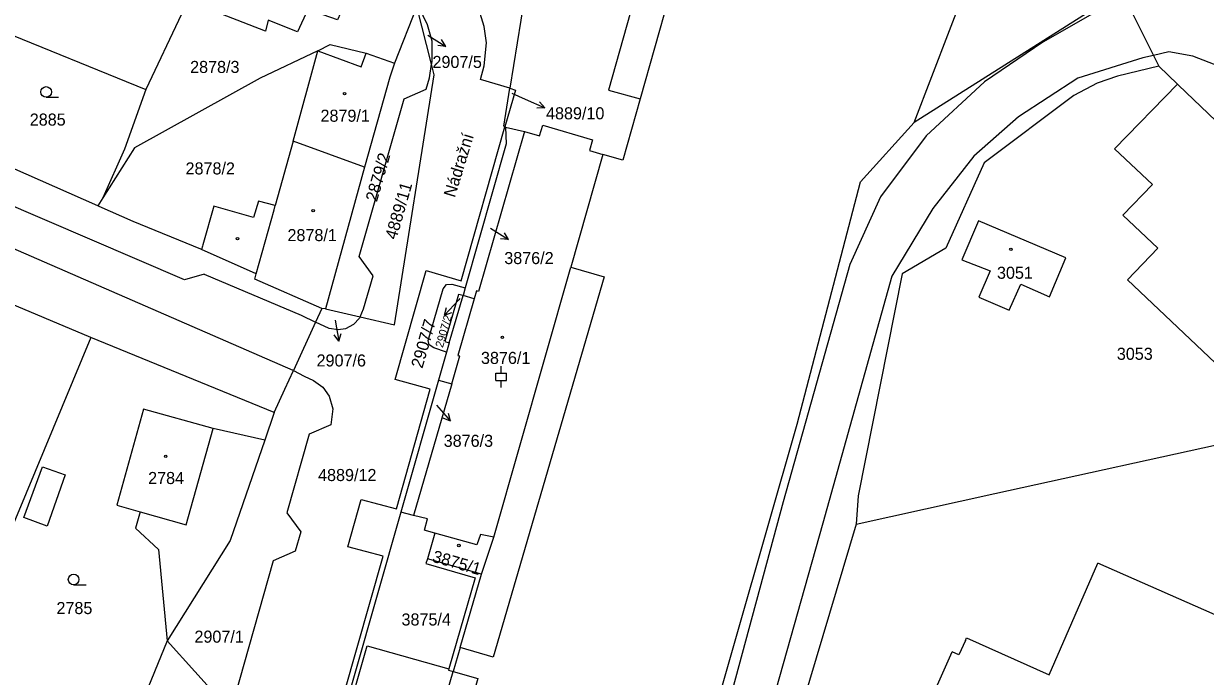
# Model space of a CAD drawing. Extents: x -527335 to -526256, y -1079142 to -1077809.
# Drawn here: x -526891.4 to -526725, y -1078806.1 to -1078714.2 of the extents above; entities that cross this region are included whole.
import ezdxf

# ---------------------------------------------------------------- set-up
doc = ezdxf.new("R2010")
doc.units = 0
for name, color, linetype in [('Vrstva 1', 7, 'Continuous'), ('Vrstva 2', 7, 'Continuous'), ('Vrstva 3', 7, 'Continuous'), ('Vrstva 4', 7, 'Continuous'), ('Vrstva 5', 7, 'Continuous'), ('Vrstva 7', 7, 'Continuous')]:
    doc.layers.add(name, color=color, linetype=linetype)

msp = doc.modelspace()

# ---------------------------------------------------------------- linework, layer by layer
at = {"layer": 'Vrstva 1'}
for p, q in [((-526796.21, -1078695.13), (-526804.6, -1078724.76)), ((-526819.43, -1078701.36), (-526822.95, -1078723.3)), ((-526736.78, -1078709.62), (-526766.02, -1078728.13)), ((-526836.05, -1078711.79), (-526839.19, -1078719.76)), ((-526833.99, -1078719.88), (-526836.05, -1078711.79)), ((-526853.47, -1078730.76), (-526850, -1078718.03)), ((-526833.92, -1078719.44), (-526833.99, -1078719.88)), ((-526834.28, -1078721.82), (-526833.99, -1078719.88)), ((-526833.6, -1078721.4), (-526833.99, -1078719.88)), ((-526728.91, -1078722.73), (-526731.58, -1078720.17)), ((-526839.2, -1078756.6), (-526833.6, -1078721.4)), ((-526823.64, -1078728.74), (-526823.55, -1078728.79)), ((-526823.55, -1078728.79), (-526820.87, -1078729.39)), ((-526880.94, -1078739.86), (-526903.84, -1078729.73)), ((-526843.4, -1078734.39), (-526853.47, -1078730.76)), ((-526843.4, -1078734.39), (-526848.91, -1078754.35)), ((-526880.24, -1078738.74), (-526880.94, -1078739.86)), ((-526881.96, -1078758.41), (-526909.05, -1078746.98)), ((-526831.48, -1078759.12), (-526829.54, -1078752.49)), ((-526849.41, -1078754.29), (-526850.31, -1078756.25)), ((-526848.91, -1078754.35), (-526849.41, -1078754.29)), ((-526848.91, -1078754.35), (-526844.03, -1078755.48)), ((-526844.03, -1078755.48), (-526843.54, -1078754.36)), ((-526850.31, -1078756.25), (-526853.42, -1078763.04)), ((-526844.03, -1078755.48), (-526844.11, -1078755.67)), ((-526844.03, -1078755.48), (-526839.2, -1078756.6)), ((-526881.96, -1078758.41), (-526900.23, -1078802.31)), ((-526856.12, -1078768.95), (-526881.96, -1078758.41)), ((-526832.99, -1078764.38), (-526838.29, -1078782.98)), ((-526856.12, -1078768.95), (-526857.46, -1078772.84)), ((-526836.49, -1078783.47), (-526838.29, -1078782.98)), ((-526774.18, -1078784.68), (-526790.21, -1078838.32)), ((-526871.22, -1078801.11), (-526877.03, -1078815.27)), ((-526863.41, -1078809.75), (-526871.22, -1078801.11)), ((-526829.95, -1078802.05), (-526830.92, -1078805.41))]:
    msp.add_line(p, q, dxfattribs=at)
for points in [[(-526766.02, -1078728.13), (-526758.54, -1078708.63), (-526747.6, -1078675.03)], [(-526796.21, -1078695.13), (-526797.53, -1078694.71), (-526797.63, -1078695.06), (-526800.78, -1078694.21), (-526809.06, -1078723.54), (-526804.6, -1078724.76)], [(-526822.95, -1078723.3), (-526827.09, -1078722.05), (-526826.54, -1078720.12), (-526826.24, -1078716.92), (-526826.57, -1078714.61), (-526827.31, -1078712.18), (-526828.95, -1078709.32), (-526834.61, -1078701.38)], [(-526736.78, -1078709.62), (-526736.47, -1078710.26), (-526732.32, -1078718.67), (-526731.58, -1078720.17)], [(-526868.26, -1078711.02), (-526869.17, -1078712.87), (-526874.21, -1078723.48)], [(-526845.53, -1078709.84), (-526847.23, -1078713.67), (-526851.39, -1078712.19), (-526852.86, -1078715.34), (-526856.99, -1078713.69), (-526857.33, -1078715.27), (-526868.26, -1078711.02)], [(-526836.01, -1078711.53), (-526835.83, -1078711.79), (-526834.6, -1078714.3), (-526833.95, -1078716.6), (-526833.92, -1078719.44)], [(-526903.84, -1078729.73), (-526895.72, -1078714.74), (-526874.21, -1078723.48)], [(-526850, -1078718.03), (-526848.26, -1078717.14), (-526843.17, -1078718.33), (-526839.19, -1078719.76)], [(-526850, -1078718.03), (-526858.12, -1078721.85), (-526875.81, -1078731.66), (-526880.24, -1078738.74)], [(-526839.19, -1078719.76), (-526839.85, -1078721.74), (-526843.4, -1078734.39)], [(-526731.58, -1078720.17), (-526737.37, -1078721.57), (-526740.22, -1078722.56), (-526743.53, -1078724.3), (-526756.16, -1078733.81), (-526761.57, -1078745.82), (-526767.69, -1078749.42), (-526773.89, -1078780.67), (-526774.18, -1078784.68)], [(-526843.54, -1078754.36), (-526842.21, -1078749.69), (-526844.14, -1078746.97), (-526837.84, -1078724.77), (-526834.74, -1078723.42), (-526834.28, -1078721.82)], [(-526728.91, -1078722.73), (-526737.79, -1078731.81), (-526732.46, -1078736.86), (-526736.62, -1078741.14), (-526731.71, -1078745.82), (-526735.95, -1078750.27), (-526722.75, -1078762.81), (-526718.49, -1078758.42), (-526714.33, -1078754.04), (-526705.71, -1078744.91)], [(-526705.71, -1078744.91), (-526728.8, -1078722.84), (-526728.91, -1078722.73)], [(-526874.21, -1078723.48), (-526877.22, -1078731.87), (-526880.24, -1078738.74)], [(-526823.64, -1078728.74), (-526823.81, -1078728.65), (-526822.95, -1078723.3)], [(-526822.95, -1078723.3), (-526822.16, -1078723.54), (-526823.64, -1078728.74)], [(-526804.6, -1078724.76), (-526807.05, -1078733.43), (-526809.84, -1078732.63)], [(-526884.44, -1079141.53), (-526861.26, -1079084.28), (-526853.99, -1079074.79), (-526822.82, -1079003.24), (-526818.77, -1078991.73), (-526809.1, -1078957.32), (-526811.39, -1078950.51), (-526823.11, -1078928.49), (-526800.47, -1078837.81), (-526799.62, -1078833.84), (-526796.71, -1078822.54), (-526795.22, -1078815.04), (-526782.49, -1078770.61), (-526773.56, -1078736.49), (-526766.02, -1078728.13)], [(-526852.48, -1078831.96), (-526854.54, -1078831.4), (-526855.56, -1078830.87), (-526856.3, -1078830.07), (-526856.84, -1078829.04), (-526856.96, -1078827.42), (-526856.79, -1078826.7), (-526851.86, -1078828.1), (-526840.8, -1078789.17), (-526845.77, -1078787.84), (-526843.88, -1078781.19), (-526838.92, -1078782.52), (-526834.15, -1078765.67), (-526839.09, -1078764.32), (-526834.71, -1078748.94), (-526829.81, -1078750.39), (-526823.64, -1078728.74)], [(-526823.55, -1078728.79), (-526823.45, -1078731.12), (-526829.23, -1078751.41), (-526829.54, -1078752.49)], [(-526820.87, -1078729.39), (-526827.37, -1078751.92), (-526827.65, -1078751.83), (-526827.97, -1078752.94), (-526829.54, -1078752.49)], [(-526820.87, -1078729.39), (-526818.77, -1078730.01), (-526818.32, -1078728.49), (-526811.29, -1078730.56), (-526811.74, -1078732.07), (-526809.84, -1078732.63)], [(-526853.47, -1078730.76), (-526855.98, -1078739.8), (-526858.36, -1078739.18), (-526859.03, -1078741.48), (-526864.64, -1078739.88), (-526866.19, -1078745.33), (-526866.24, -1078745.51), (-526866.37, -1078745.99)], [(-526809.84, -1078732.63), (-526814.37, -1078748.5), (-526809.68, -1078749.84), (-526825.28, -1078803.4), (-526829.95, -1078802.05)], [(-526866.37, -1078745.99), (-526866.48, -1078745.94), (-526876, -1078742.04), (-526880.77, -1078739.94), (-526880.94, -1078739.86)], [(-526751, -1078750.87), (-526746.96, -1078752.64), (-526744.65, -1078747.16), (-526756.93, -1078741.98), (-526759.3, -1078747.43), (-526755.3, -1078749.01), (-526756.92, -1078752.7), (-526752.65, -1078754.52), (-526751, -1078750.87)], [(-526849.41, -1078754.29), (-526858.86, -1078750.18), (-526858.65, -1078749.42), (-526866.37, -1078745.99)], [(-526829.54, -1078752.49), (-526830.17, -1078752.32), (-526832.08, -1078758.95), (-526831.48, -1078759.12)], [(-526844.11, -1078755.67), (-526844.96, -1078756.57), (-526846.07, -1078757.15), (-526847.14, -1078757.33), (-526848.4, -1078757.1), (-526850.31, -1078756.25)], [(-526831.48, -1078759.12), (-526831.87, -1078760.46), (-526832.99, -1078764.38)], [(-526853.42, -1078763.04), (-526851.9, -1078763.85), (-526850.58, -1078764.43), (-526849.29, -1078765.38), (-526848.37, -1078766.67), (-526847.89, -1078768.42), (-526848.14, -1078770.69), (-526851.19, -1078772.01), (-526854.35, -1078783.07), (-526852.4, -1078785.74), (-526853.18, -1078788.48), (-526856.25, -1078789.82), (-526861.71, -1078809.08)], [(-526856.12, -1078768.95), (-526854.62, -1078765.66), (-526853.42, -1078763.04)], [(-526832.99, -1078764.38), (-526831.12, -1078764.89), (-526836.49, -1078783.47)], [(-526857.46, -1078772.84), (-526864.73, -1078771.19), (-526874.53, -1078768.46), (-526878.3, -1078782.01), (-526875.01, -1078782.94), (-526875.66, -1078785.24), (-526872.42, -1078788.23), (-526871.22, -1078801.11)], [(-526857.46, -1078772.84), (-526862.33, -1078786.99), (-526871.22, -1078801.11)], [(-526774.18, -1078784.68), (-526754.63, -1078780.37), (-526719.57, -1078772.65)], [(-526838.29, -1078782.98), (-526851.34, -1078828.74), (-526852.48, -1078831.96)], [(-526833.51, -1078785.92), (-526834.66, -1078785.6), (-526834.94, -1078785.52), (-526834.53, -1078783.94), (-526836.49, -1078783.47)], [(-526833.51, -1078785.92), (-526834.56, -1078789.57), (-526834.76, -1078790.21), (-526827.84, -1078792.21), (-526831.53, -1078805.04)], [(-526829.95, -1078802.05), (-526826.96, -1078791.72), (-526825.22, -1078786.49), (-526827.08, -1078786.14), (-526827.6, -1078787.59), (-526833.51, -1078785.92)], [(-526852.48, -1078831.96), (-526849.88, -1078832.66), (-526848.34, -1078832.64), (-526847.17, -1078832.15), (-526846.16, -1078831.02), (-526845.7, -1078829.8), (-526850.63, -1078828.45), (-526843.06, -1078801.82), (-526831.53, -1078805.04)], [(-526830.92, -1078805.41), (-526827.43, -1078806.4), (-526834.91, -1078832.86), (-526838.57, -1078831.82)], [(-526838.57, -1078831.82), (-526838.51, -1078831.59), (-526830.92, -1078805.41)], [(-526831.53, -1078805.04), (-526831.59, -1078805.23), (-526830.92, -1078805.41)]]:
    msp.add_lwpolyline(points, dxfattribs=at)
at = {"layer": 'Vrstva 3'}
for p, q in [((-526888.23, -1078724.56), (-526886.48, -1078724.56)), ((-526824.18, -1078763.43), (-526824.18, -1078762.43)), ((-526824.93, -1078763.43), (-526823.43, -1078763.43)), ((-526824.93, -1078764.43), (-526824.93, -1078763.43)), ((-526824.93, -1078764.43), (-526823.43, -1078764.43)), ((-526824.18, -1078765.43), (-526824.18, -1078764.43)), ((-526823.43, -1078764.43), (-526823.43, -1078763.43)), ((-526884.37, -1078793.22), (-526882.62, -1078793.22))]:
    msp.add_line(p, q, dxfattribs=at)
for centre in [(-526888.23, -1078723.81), (-526884.37, -1078792.47)]:
    msp.add_circle(centre, 0.75, dxfattribs=at)
at = {"layer": 'Vrstva 4'}
for p, q in [((-526738.29, -1078711.31), (-526747.88, -1078716.79)), ((-526747.88, -1078716.79), (-526756.12, -1078722.39)), ((-526850, -1078718.03), (-526843.87, -1078720.28)), ((-526843.87, -1078720.28), (-526843.17, -1078718.33)), ((-526733.79, -1078719.02), (-526742.97, -1078721.85)), ((-526732.32, -1078718.67), (-526733.79, -1078719.02)), ((-526730.13, -1078718.15), (-526732.32, -1078718.67)), ((-526726.79, -1078718.76), (-526730.13, -1078718.15)), ((-526723.03, -1078720.23), (-526726.79, -1078718.76)), ((-526756.12, -1078722.39), (-526764.31, -1078729.99)), ((-526742.97, -1078721.85), (-526751.34, -1078727.31)), ((-526751.34, -1078727.31), (-526757.6, -1078732.85)), ((-526764.31, -1078729.99), (-526770.73, -1078738.59)), ((-526757.6, -1078732.85), (-526763.39, -1078740.22)), ((-526868.74, -1078750.29), (-526906.55, -1078734.05)), ((-526770.73, -1078738.59), (-526775.09, -1078748.11)), ((-526858.65, -1078749.42), (-526856.15, -1078740.41)), ((-526856.15, -1078740.41), (-526855.98, -1078739.8)), ((-526763.39, -1078740.22), (-526769.14, -1078749.74)), ((-526901.75, -1078741.96), (-526853.5, -1078762.97)), ((-526865.98, -1078749.45), (-526868.74, -1078750.29)), ((-526865.98, -1078749.45), (-526852.34, -1078755.25)), ((-526825.22, -1078786.49), (-526814.37, -1078748.5)), ((-526775.09, -1078748.11), (-526784.46, -1078781.51)), ((-526832.35, -1078751.52), (-526831.87, -1078750.94)), ((-526831.87, -1078750.94), (-526831.1, -1078750.88)), ((-526831.1, -1078750.88), (-526829.23, -1078751.41)), ((-526769.14, -1078749.74), (-526778.89, -1078784.53)), ((-526834.43, -1078758.82), (-526832.35, -1078751.52)), ((-526827.97, -1078752.94), (-526830.27, -1078760.91)), ((-526852.34, -1078755.25), (-526850.31, -1078756.25)), ((-526834.3, -1078759.44), (-526834.43, -1078758.82)), ((-526833.67, -1078759.85), (-526834.3, -1078759.44)), ((-526831.87, -1078760.46), (-526833.67, -1078759.85)), ((-526831.12, -1078764.89), (-526829.99, -1078760.99)), ((-526830.27, -1078760.91), (-526829.99, -1078760.99)), ((-526853.42, -1078763.04), (-526853.5, -1078762.97)), ((-526868.54, -1078784.76), (-526864.73, -1078771.19)), ((-526891.36, -1078783.74), (-526888.74, -1078776.62)), ((-526888.74, -1078776.62), (-526885.57, -1078777.74)), ((-526885.57, -1078777.74), (-526888.09, -1078784.94)), ((-526784.46, -1078781.51), (-526793.55, -1078815.2)), ((-526888.09, -1078784.94), (-526891.36, -1078783.74)), ((-526875.01, -1078782.94), (-526868.54, -1078784.76)), ((-526778.89, -1078784.53), (-526788.56, -1078818.84)), ((-526826.96, -1078791.72), (-526834.56, -1078789.57)), ((-526747.01, -1078805.88), (-526740.14, -1078790.15)), ((-526719.94, -1078799.06), (-526740.14, -1078790.15)), ((-526758.79, -1078801.05), (-526759.7, -1078803.09)), ((-526758.79, -1078801.05), (-526758.62, -1078800.66)), ((-526758.62, -1078800.66), (-526747.01, -1078805.88)), ((-526771.41, -1078826.69), (-526760.66, -1078802.66)), ((-526759.7, -1078803.09), (-526760.66, -1078802.66))]:
    msp.add_line(p, q, dxfattribs=at)
at = {"layer": 'Vrstva 5'}
for centre in [(-526846.22, -1078724.06), (-526850.64, -1078740.54), (-526861.3, -1078744.47), (-526752.39, -1078745.98), (-526824, -1078758.37), (-526871.4, -1078775.12), (-526830.12, -1078787.68)]:
    msp.add_circle(centre, 0.175, dxfattribs=at)
at = {"layer": 'Vrstva 7'}
for p, q in [((-526834.51, -1078715.81), (-526831.96, -1078717.4)), ((-526831.96, -1078717.4), (-526833.08, -1078717.29)), ((-526831.96, -1078717.4), (-526832.55, -1078716.45)), ((-526822.67, -1078723.99), (-526820.78, -1078724.84)), ((-526820.78, -1078724.84), (-526818.04, -1078726.06)), ((-526818.04, -1078726.06), (-526819.16, -1078726.11)), ((-526818.04, -1078726.06), (-526818.75, -1078725.2)), ((-526825.68, -1078743.01), (-526823.14, -1078744.6)), ((-526823.14, -1078744.6), (-526824.25, -1078744.49)), ((-526823.14, -1078744.6), (-526823.72, -1078743.65)), ((-526829.97, -1078752.9), (-526830.12, -1078753.06)), ((-526830.12, -1078753.06), (-526832.17, -1078755.26)), ((-526832.17, -1078755.26), (-526831.85, -1078754.18)), ((-526847.53, -1078755.95), (-526847.01, -1078758.91)), ((-526832.17, -1078755.26), (-526831.12, -1078754.86)), ((-526847.01, -1078758.91), (-526846.69, -1078757.83)), ((-526847.01, -1078758.91), (-526847.68, -1078758.01)), ((-526833.27, -1078767.9), (-526831.3, -1078770.17)), ((-526831.3, -1078770.17), (-526831.58, -1078769.08)), ((-526831.3, -1078770.17), (-526832.34, -1078769.74))]:
    msp.add_line(p, q, dxfattribs=at)

# ---------------------------------------------------------------- texts
at = {"layer": 'Vrstva 2'}
for s, p in [('2878/3', (-526867.97, -1078721.14)), ('2907/5', (-526833.84, -1078720.44)), ('2879/1', (-526849.61, -1078728.01)), ('4889/10', (-526817.85, -1078727.67)), ('2885', (-526890.55, -1078728.55)), ('2878/2', (-526868.61, -1078735.43)), ('2878/1', (-526854.26, -1078744.82)), ('3876/2', (-526823.73, -1078748.05)), ('3051', (-526754.35, -1078750.12)), ('2907/6', (-526850.16, -1078762.47)), ('3876/1', (-526827.01, -1078762.11)), ('3053', (-526737.47, -1078761.53)), ('3876/3', (-526832.26, -1078773.78)), ('2784', (-526873.88, -1078779.02)), ('4889/12', (-526849.95, -1078778.6)), ('2785', (-526886.79, -1078797.33)), ('3875/4', (-526838.2, -1078798.94)), ('2907/1', (-526867.36, -1078801.36))]:
    msp.add_text(s, height=1.7, dxfattribs=at).set_placement(p)
for s, height, rotation, p in [('2879/2', 1.7, 74, (-526841.67, -1078739.38)), ('4889/11', 1.7, 74, (-526838.93, -1078744.7)), ('2907/7', 1.7, 74, (-526835.26, -1078762.82)), ('2907/2', 1.139, 74, (-526832.38, -1078759.89)), ('3875/1', 1.7, 344, (-526833.98, -1078789.94))]:
    msp.add_text(s, height=height, rotation=rotation, dxfattribs=at).set_placement(p)
at = {"layer": 'Vrstva 7'}
msp.add_text('Nádražní', height=1.7, rotation=73, dxfattribs=at).set_placement((-526830.69, -1078738.78))

doc.saveas('drawing.dxf')
